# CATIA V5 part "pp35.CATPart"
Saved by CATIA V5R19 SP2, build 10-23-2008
Part number: pp35
Bounding box of the stored display mesh (mm): x -15 to -10, y -422.25 to -244.785, z -52.25 to 37.736
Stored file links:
  C:\Users\Welcome\Documents\thinkm2\pp35.CATPart
  C:\Users\Welcome\Documents\thinkm2\Brasmeca.CATProduct
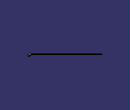
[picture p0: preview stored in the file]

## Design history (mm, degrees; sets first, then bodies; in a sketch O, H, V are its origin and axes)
AxisSystem1: origin (0, 0, 0), X (1, 0, 0), Y (0, 1, 0), Z (0, 0, 1)
Set1
  Plane1: linked copy from another document
  Line1: linked copy from another document
  Plane2: linked copy from another document
  Sketch1, origin (5, 0, 0), H (0, 1, 0), V (0, 0, 1), geometry linked from another document
Body1 (main body)
  Sketch2 on Plane1, origin (-15, 0, 0), H (0, 1, 0), V (0, 0, 1)
    circle A1 centre (-420, -50) radius 2.25
    reference projected point E1 (-420, -50) from Line1
    radius A1 = 2.25
    distance A1 E1 = 2.25
  Pad1: profile Sketch2, direction (1, 0, 0), length 5
  Sketch3 on Plane2, origin (0, -206, -103), H (-1, 0, 0), V (0, -0.4472, 0.8944)
    line L1 (14.9554, 143.3732) -> (13.2544, 143.3732)
    line L2 (13.2544, 143.3732) -> (13.2544, 142.6259)
    line L3 (13.2544, 142.6259) -> (14.9554, 142.6259)
    line L4 (14.9554, 142.6259) -> (14.9554, 143.3732)
  Pad2: profile Sketch3, direction (0, -0.8944, -0.4472), length 167
  Pad3: profile Sketch3, direction (0, 0.8944, 0.4472), length 27.95
  Pocket1: profile Sketch1, direction (-1, 0, 0), length 27.95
